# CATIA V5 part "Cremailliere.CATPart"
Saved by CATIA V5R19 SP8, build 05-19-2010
Part number: Cremailliere
Bounding box of the stored display mesh (mm): x 0 to 8, y 0 to 217.533, z -19.989 to 21.75
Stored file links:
  D:\Mes documents\2020 TSTI2D\2I2D\SERRE\EE\CATIA\Cremailliere.CATPart
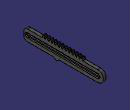
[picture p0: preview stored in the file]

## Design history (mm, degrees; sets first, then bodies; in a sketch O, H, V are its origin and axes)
Body1 (main body)
  Sketch1 on yz-plane, origin (0, 0, 0), H (0, 1, 0), V (0, 0, 1)
    line L1 (202.544, -15) -> (96.544, -15)
    line L2 (0, -5) -> (0, 5)
    line L3 (10, 15) -> (50, 15)
    point P1 (202.544, 15)
    point P2 (202.544, -15)
    point P3 (0, -15)
    point P4 (0, 15)
    construction line L4 (-115.8191, 0) -> (154.6067, 0)
    point P5 (-115.8191, 0)
    arc A1 centre (202.544, 0) radius 15 from (202.544, -15) to (202.544, 15) ccw
    point P7 (202.544, 0)
    construction line L5 (10, 0) -> (202.544, 0)
    point P8 (10, 0)
    point P9 (202.544, 0)
    line L6 (10, 3) -> (202.544, 3)
    line L7 (202.544, -3) -> (10, -3)
    arc A2 centre (202.544, 0) radius 3 from (202.544, 3) to (202.544, -3) cw
    arc A3 centre (10, 0) radius 3 from (10, -3) to (10, 3) cw
    point P14 (50, 15)
    line L8 (50, 15) -> (51.3644, 18.75)
    point P15 (51.3644, 18.75)
    line L9 (51.3644, 18.75) -> (52.4559, 21.75)
    point P16 (52.4559, 21.75)
    line L10 (52.4559, 21.75) -> (54.9849, 21.75)
    point P17 (54.9849, 21.75)
    line L11 (54.9849, 21.75) -> (56.0764, 18.75)
    point P18 (56.0764, 18.75)
    line L12 (56.0764, 18.75) -> (57.4408, 15)
    point P19 (57.4407, 15)
    construction line L13 (53.7204, 26.965) -> (53.7204, 8.8772)
    point P22 (59.4247, 15)
    line L14 (57.4407, 15) -> (59.4247, 15)
    point P23 (61.8809, 21.75)
    point P24 (64.4099, 21.75)
    point P25 (65.5015, 18.7499)
    point P27 (68.85, 15)
    line L15 (61.8809, 21.75) -> (64.4099, 21.75)
    line L16 (64.4099, 21.75) -> (65.5015, 18.7499)
    line L17 (65.5015, 18.7499) -> (66.866, 15)
    line L18 (66.866, 15) -> (68.85, 15)
    construction line L19 (63.1454, 26.965) -> (63.1454, 8.8772)
    point P30 (60.7892, 18.7499)
    line L20 (60.7892, 18.7499) -> (61.8809, 21.75)
    point P31 (59.4248, 15)
    line L21 (59.4248, 15) -> (60.7892, 18.7499)
    point P32 (71.3059, 21.75)
    point P33 (73.8349, 21.75)
    point P34 (74.922, 18.7621)
    point P36 (78.2747, 15)
    line L22 (71.3059, 21.75) -> (73.8349, 21.75)
    line L23 (73.8349, 21.75) -> (74.922, 18.7621)
    line L24 (74.922, 18.7621) -> (76.2908, 15)
    line L25 (76.2907, 15) -> (78.2747, 15)
    construction line L26 (72.5704, 26.965) -> (72.5704, 8.8772)
    point P39 (70.2188, 18.7621)
    line L27 (70.2188, 18.7621) -> (71.3059, 21.75)
    point P40 (68.85, 15)
    line L28 (68.85, 15) -> (70.2188, 18.7621)
    point P41 (80.7309, 21.75)
    point P42 (83.2599, 21.75)
    point P43 (84.3521, 18.7482)
    point P45 (87.7, 15)
    line L29 (80.7309, 21.75) -> (83.2599, 21.75)
    line L30 (83.2599, 21.75) -> (84.3521, 18.7482)
    line L31 (84.3521, 18.7482) -> (85.716, 15)
    line L32 (85.716, 15) -> (87.7, 15)
    construction line L33 (81.9954, 26.965) -> (81.9954, 8.8772)
    point P48 (79.6386, 18.7482)
    line L34 (79.6386, 18.7482) -> (80.7309, 21.75)
    point P49 (78.2747, 15)
    line L35 (78.2748, 15) -> (79.6386, 18.7482)
    point P50 (90.1559, 21.75)
    point P51 (92.6849, 21.75)
    point P52 (93.7778, 18.7461)
    point P54 (97.1247, 15)
    line L36 (90.1559, 21.75) -> (92.6849, 21.75)
    line L37 (92.6849, 21.75) -> (93.7778, 18.7461)
    line L38 (93.7778, 18.7461) -> (95.1408, 15)
    line L39 (95.1407, 15) -> (97.1247, 15)
    construction line L40 (91.4204, 26.965) -> (91.4204, 8.8772)
    point P57 (89.063, 18.7461)
    line L41 (89.063, 18.7461) -> (90.1559, 21.75)
    point P58 (87.7, 15)
    line L42 (87.7, 15) -> (89.063, 18.7461)
    point P59 (99.5809, 21.75)
    point P60 (102.1099, 21.75)
    point P61 (103.2026, 18.747)
    point P63 (106.55, 15)
    line L43 (99.5809, 21.75) -> (102.1099, 21.75)
    line L44 (102.1099, 21.75) -> (103.2026, 18.747)
    line L45 (103.2026, 18.747) -> (104.566, 15)
    line L46 (104.566, 15) -> (106.55, 15)
    construction line L47 (100.8454, 26.965) -> (100.8454, 8.8772)
    point P66 (98.4882, 18.747)
    line L48 (98.4882, 18.747) -> (99.5809, 21.75)
    point P67 (97.1247, 15)
    line L49 (97.1248, 15) -> (98.4882, 18.747)
    point P68 (109.0059, 21.75)
    point P69 (111.5349, 21.75)
    point P70 (112.6266, 18.7494)
    point P72 (115.9748, 15)
    line L50 (109.0059, 21.75) -> (111.5349, 21.75)
    line L51 (111.5349, 21.75) -> (112.6266, 18.7494)
    line L52 (112.6266, 18.7494) -> (113.9908, 15)
    line L53 (113.9907, 15) -> (115.9747, 15)
    construction line L54 (110.2704, 26.965) -> (110.2704, 8.8772)
    point P75 (107.9142, 18.7494)
    line L55 (107.9142, 18.7494) -> (109.0059, 21.75)
    point P76 (106.55, 15)
    line L56 (106.55, 15) -> (107.9142, 18.7494)
    point P77 (118.4309, 21.75)
    point P78 (120.9599, 21.75)
    point P79 (122.0518, 18.7491)
    point P81 (125.4, 15)
    line L57 (118.4309, 21.75) -> (120.9599, 21.75)
    line L58 (120.9599, 21.75) -> (122.0518, 18.7491)
    line L59 (122.0518, 18.7491) -> (123.416, 15)
    line L60 (123.416, 15) -> (125.4, 15)
    construction line L61 (119.6954, 26.965) -> (119.6954, 8.8772)
    point P84 (117.3389, 18.7491)
    line L62 (117.3389, 18.7491) -> (118.4309, 21.75)
    point P85 (115.9748, 15)
    line L63 (115.9747, 15) -> (117.3389, 18.7491)
    point P86 (127.8559, 21.75)
    point P87 (130.3849, 21.75)
    point P88 (131.477, 18.7482)
    point P90 (134.8248, 15)
    line L64 (127.8559, 21.75) -> (130.3849, 21.75)
    line L65 (130.3849, 21.75) -> (131.477, 18.7482)
    line L66 (131.477, 18.7482) -> (132.8408, 15)
    line L67 (132.8407, 15) -> (134.8247, 15)
    construction line L68 (129.1204, 26.965) -> (129.1204, 8.8772)
    point P93 (126.7637, 18.7482)
    line L69 (126.7637, 18.7482) -> (127.8559, 21.75)
    point P94 (125.4, 15)
    line L70 (125.4, 15) -> (126.7637, 18.7482)
    point P95 (137.2809, 21.75)
    point P96 (139.8099, 21.75)
    point P97 (140.9016, 18.7496)
    point P99 (144.25, 15)
    line L71 (137.2809, 21.75) -> (139.8099, 21.75)
    line L72 (139.8099, 21.75) -> (140.9016, 18.7496)
    line L73 (140.9016, 18.7496) -> (142.266, 15)
    line L74 (142.266, 15) -> (144.25, 15)
    construction line L75 (138.5454, 26.965) -> (138.5454, 8.8772)
    point P102 (136.1891, 18.7496)
    line L76 (136.1891, 18.7496) -> (137.2809, 21.75)
    point P103 (134.8247, 15)
    line L77 (134.8248, 15) -> (136.1891, 18.7496)
    point P104 (146.7059, 21.75)
    point P105 (149.2349, 21.75)
    point P106 (150.327, 18.7482)
    point P107 (151.6908, 15)
    line L78 (146.7059, 21.75) -> (149.2349, 21.75)
    line L79 (149.2349, 21.75) -> (150.327, 18.7482)
    line L80 (150.327, 18.7482) -> (151.6908, 15)
    construction line L81 (147.9704, 26.965) -> (147.9704, 8.8772)
    point P110 (145.6137, 18.7482)
    line L82 (145.6137, 18.7482) -> (146.7059, 21.75)
    point P111 (144.25, 15)
    line L83 (144.25, 15) -> (145.6137, 18.7482)
    point P112 (151.6908, 15)
    point P113 (153.6748, 15)
    point P114 (156.1309, 21.75)
    point P115 (158.6599, 21.75)
    point P116 (159.7202, 18.8359)
    point P119 (157.3954, 26.965)
    point P120 (155.0705, 18.8359)
    point P121 (153.6748, 15)
    line L84 (151.6908, 15) -> (153.6748, 15)
    line L85 (156.1309, 21.75) -> (158.6599, 21.75)
    line L86 (158.6599, 21.75) -> (159.7202, 18.8359)
    line L87 (159.7202, 18.8359) -> (161.116, 15)
    line L88 (155.0705, 18.8359) -> (156.1309, 21.75)
    line L89 (153.6748, 15) -> (155.0705, 18.8359)
    line L90 (161.116, 15) -> (202.544, 15)
    point P122 (202.544, 15)
    construction line L91 (157.3954, 18.75) -> (157.3954, 24.026)
    construction line L92 (89.044, -12.8653) -> (89.044, -22.1347)
    line L93 (87.544, -19.5) -> (81.544, -15)
    point P126 (81.544, -15)
    line L94 (90.544, -19.5) -> (96.544, -15)
    point P127 (96.544, -15)
    line L95 (81.544, -15) -> (10, -15)
    arc A4 centre (89.044, -17.5) radius 2.5 from (87.544, -19.5) to (90.544, -19.5) ccw
    point P128 (89.044, -17.5)
    point P129 (68.5465, -18.0125)
    arc A5 centre (10, 5) radius 10 from (0, 5) to (10, 15) cw
    arc A6 centre (10, -5) radius 10 from (0, -5) to (10, -15) ccw
    construction line L96 (51.3644, 18.75) -> (56.0764, 18.75)
    construction line L97 (60.7892, 18.7499) -> (65.5015, 18.7499)
    construction line L98 (70.2188, 18.7621) -> (74.922, 18.7621)
    construction line L99 (79.6386, 18.7482) -> (84.3521, 18.7482)
    construction line L100 (89.063, 18.7461) -> (93.7778, 18.7461)
    construction line L101 (98.4882, 18.747) -> (103.2026, 18.747)
    construction line L102 (107.9142, 18.7494) -> (112.6266, 18.7494)
    construction line L103 (117.3389, 18.7491) -> (122.0518, 18.7491)
    construction line L104 (126.7637, 18.7482) -> (131.477, 18.7482)
    construction line L105 (136.1891, 18.7496) -> (140.9016, 18.7496)
    construction line L106 (150.327, 18.7482) -> (145.6137, 18.7482)
    axis line L107 (155.0705, 18.8359) -> (159.7202, 18.8359)
    radius A1 = 15
    distance L5 L6 = 3
    distance P8 L2 = 10
    length L10 = 2.529
    distance L10 L3 = 6.75
    length L14 = 1.984
    length L15 = 2.529
    length L18 = 1.984
    distance L15 L3 = 6.75 (reference)
    length L22 = 2.529
    length L25 = 1.984
    distance L22 L3 = 6.75 (reference)
    length L29 = 2.529
    length L32 = 1.984
    distance L29 L3 = 6.75 (reference)
    length L36 = 2.529
    length L39 = 1.984
    distance L36 L3 = 6.75 (reference)
    length L46 = 1.984
    length L43 = 2.529
    distance L43 L3 = 6.75 (reference)
    length L53 = 1.984
    length L50 = 2.529
    distance L50 L3 = 6.75 (reference)
    length L60 = 1.984
    length L57 = 2.529
    distance L57 L3 = 6.75 (reference)
    length L67 = 1.984
    length L64 = 2.529
    distance L64 L3 = 6.75 (reference)
    length L74 = 1.984
    length L71 = 2.529
    distance L71 L3 = 6.75 (reference)
    length L78 = 2.529
    distance L78 L3 = 6.75 (reference)
    distance L13 L19 = 9.425
    distance L19 L26 = 9.425
    distance L26 L33 = 9.425
    distance L33 L40 = 9.425
    distance L40 L47 = 9.425
    distance L47 L54 = 9.425
    distance L54 L61 = 9.425
    distance L61 L68 = 9.425
    distance L68 L75 = 9.425
    distance L75 L81 = 9.425
    length L85 = 2.529
    length L84 = 1.984
    distance L85 L3 = 6.75 (reference)
    distance P2 P3 = 202.544
    distance P126 P127 = 15
    radius A4 = 2.5
    distance P128 L95 = 2.5
    distance L92 P9 = 113.5
    distance P3 P4 = 30
    distance P4 P14 = 50
    radius A5 = 10
    radius A6 = 10
    distance L81 L91 = 9.425
    length L96 = 4.712
    distance L13 L2 = 53.7204
    length L97 = 4.7123
    length L98 = 4.7032
    length L99 = 4.7135
    length L100 = 4.7148
    length L101 = 4.7144
    length L102 = 4.7124
    length L103 = 4.7129
    length L104 = 4.7133
    length L105 = 4.7125
    length L106 = 4.7133
    length L107 = 4.6497
    horizontal: L1 H, L3 H, L4 H, L5 H, L10 H, L14 H, L18 H, L15 H, L22 H, L25 H, L29 H, L32 H, L36 H, L39 H, L43 H, L46 H, L53 H, L50 H, L60 H, L57 H, L67 H, L64 H, L74 H, L71 H, L78 H, L84 H, L85 H, L90 H, L95 H, L96 H
    vertical: L2 V, L13 V, L19 V, L26 V, L33 V, L40 V, L47 V, L54 V, L61 V, L68 V, L75 V, L81 V, L91 V, L92 V
    equidistance: L1 L3 O
    coincidence: P5 H, L2 V, P8 L4, P9 P7, P19 L3, L18 L14, L25 L18, L32 L25, L32 L39, L39 L46, L46 L53, L60 L53, L67 L60, L74 L67, L15 L10, P22 P31, L22 L15, P27 P40, L29 L22, P49 P36, L36 L29, P58 P45, L43 L36, P67 P54, L50 L43, L57 L50, P76 P63, P72 P85, L57 L64, L64 L71, L78 L71, P94 P81, P90 P103, P111 P99, P121 P113, L74 L84, L85 L78, P107 P112, P122 P1, P126 L1, L1 L95, L2 P4, L3 P4, L2 P3, L95 P3
    tangency: A2 L6, A3 L6, A2 L7, A3 L7, L90 A1, A4 L94, A4 L93, A5 L2, A5 L3, A6 L2, A6 L95
    parallelism: L9 L8, L12 L11, L20 L21, L17 L16, L24 L23, L27 L28, L31 L30, L34 L35, L41 L42, L38 L37, L48 L49, L45 L44, L55 L56, L52 L51, L62 L63, L59 L58, L66 L65, L69 L70, L76 L77, L73 L72, L80 L79, L82 L83, L87 L86, L88 L89
    symmetry: P16 P17 L13, P23 P24 L19, P32 P33 L26, P41 P42 L33, P50 P51 L40, P59 P60 L47, P68 P69 L54, P77 P78 L61, P86 P87 L68, P95 P96 L75, P104 P105 L81, P114 P115 L91, P126 P127 L92, P15 P18 L13, P30 P25 L19, P39 P34 L26, P48 P43 L33, P57 P52 L40, P61 P66 L47, P75 P70 L54, P84 P79 L61, P93 P88 L68, P102 P97 L75, P110 P106 L81, P120 P116 L91
    midpoint: P128 L92
  Pad1: profile Sketch1, direction (1, 0, 0), length 8
  Sketch2 on end face of Pad1, origin (8, 0, 0), H (0, 1, 0), V (0, 0, 1)
    projected line E1 (10, -3) -> (202.544, -3) from edge [end face of Pad1 | face of Pad1 from Sketch1.L7]
    projected line E2 (202.544, 3) -> (10, 3) from edge [end face of Pad1 | face of Pad1 from Sketch1.L6]
    projected arc E3 centre (10, 0) radius 3 from (10, 3) to (10, -3) ccw from edge [end face of Pad1 | face of Pad1 from Sketch1.A3]
    projected arc E4 centre (202.544, 0) radius 3 from (202.544, -3) to (202.544, 3) ccw from edge [end face of Pad1 | face of Pad1 from Sketch1.A2]
  Pocket1: profile Sketch2, direction (-1, 0, 0), length 4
